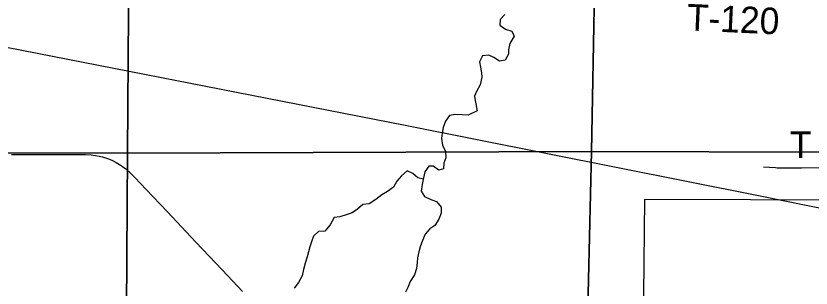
# Model space of a CAD drawing. Extents: x 0 to 34, y 0 to 22.
# Drawn here: x 4.352 to 5.204, y 18.771 to 19.063 of the extents above; entities that cross this region are included whole.
import ezdxf

# ---------------------------------------------------------------- set-up
doc = ezdxf.new("R2010")
doc.units = 0
for name, color, linetype in [('GM_X_County_Road', 7, 'Continuous'), ('GM_X_Minor_River', 7, 'Continuous'), ('GM_X_Rail_Line', 7, 'Continuous'), ('GM_X_Section', 7, 'Continuous'), ('GM_X_Township_Road', 7, 'Continuous'), ('GM_X_Township_Road_Text', 7, 'Continuous')]:
    doc.layers.add(name, color=color, linetype=linetype)

msp = doc.modelspace()

# ---------------------------------------------------------------- linework, layer by layer
at = {"layer": 'GM_X_County_Road'}
msp.add_lwpolyline([(4.3471, 18.91407), (4.37396, 18.91403), (4.40566, 18.91404), (4.42322, 18.91401), (4.42638, 18.91401), (4.43259, 18.91364), (4.43732, 18.91302), (4.44114, 18.91241), (4.44452, 18.91163), (4.44678, 18.91101), (4.44908, 18.91027), (4.452, 18.90912), (4.45599, 18.9074), (4.45932, 18.90563), (4.46286, 18.90357), (4.46619, 18.90131), (4.46973, 18.89864), (4.47429, 18.89461), (4.47939, 18.8896), (4.49153, 18.87673), (4.51382, 18.85305), (4.5292, 18.83679), (4.54475, 18.82025), (4.56605, 18.79764), (4.57889, 18.78411), (4.59481, 18.7673)], dxfattribs=at)
at = {"layer": 'GM_X_Minor_River'}
for points in [[(4.87582, 19.0644), (4.87086, 19.05892), (4.87063, 19.05285), (4.87648, 19.04864), (4.88347, 19.04632), (4.88571, 19.04118), (4.88131, 19.03323), (4.87975, 19.02641), (4.87972, 19.02166), (4.87627, 19.01542), (4.8702, 19.01431), (4.86398, 19.01834), (4.85888, 19.02084), (4.85187, 19.01993), (4.84861, 19.01368), (4.8499, 19.00798), (4.851, 19.00171), (4.85116, 18.99696), (4.8494, 18.989), (4.84557, 18.98181), (4.84327, 18.97688), (4.84399, 18.97194), (4.84635, 18.9611)], [(4.84635, 18.9611), (4.8364, 18.95642), (4.82995, 18.95666), (4.82293, 18.9571), (4.81647, 18.956), (4.81225, 18.94977), (4.80993, 18.94296), (4.80874, 18.93709), (4.80813, 18.9314), (4.80922, 18.92418), (4.81221, 18.91752), (4.81273, 18.91068), (4.81041, 18.90482), (4.81017, 18.89875), (4.80504, 18.89746), (4.79919, 18.90149), (4.79445, 18.90171), (4.79004, 18.89567), (4.78885, 18.88904), (4.7871, 18.88203), (4.7861, 18.87483), (4.78966, 18.8693), (4.79666, 18.86602), (4.80271, 18.8637), (4.8076, 18.85759), (4.80774, 18.85114), (4.80523, 18.84471), (4.80082, 18.8381), (4.79548, 18.83434), (4.79051, 18.82888), (4.78761, 18.82207), (4.78509, 18.81507), (4.78373, 18.80996), (4.78235, 18.80332), (4.78175, 18.79821), (4.78113, 18.79195), (4.779, 18.78532), (4.77439, 18.77796), (4.77188, 18.77153), (4.76938, 18.76661)], [(4.78854, 18.88781), (4.78278, 18.88928), (4.77712, 18.89368), (4.77126, 18.89657), (4.76515, 18.89131), (4.76018, 18.88546), (4.75653, 18.87904), (4.75004, 18.87453), (4.74413, 18.87078), (4.73765, 18.8659), (4.73059, 18.86121), (4.72376, 18.86069), (4.71803, 18.85561), (4.71212, 18.85167), (4.70565, 18.84963), (4.69919, 18.84721), (4.69292, 18.8465), (4.68869, 18.83894), (4.68295, 18.83215), (4.6763, 18.83163), (4.67077, 18.82655), (4.66883, 18.82163), (4.66689, 18.81519), (4.66533, 18.80989), (4.66397, 18.80459), (4.66202, 18.79758), (4.66007, 18.79077), (4.6585, 18.78395), (4.65485, 18.77696), (4.65025, 18.77073)]]:
    msp.add_lwpolyline(points, dxfattribs=at)
at = {"layer": 'GM_X_Rail_Line'}
msp.add_lwpolyline([(2.6, 19.37601), (2.66227, 19.36364), (3.09112, 19.27847), (3.48984, 19.19924), (3.90426, 19.11632), (4.22655, 19.05166), (4.7691, 18.94555), (5.14758, 18.87009), (5.40664, 18.81773), (5.47207, 18.80597), (5.50091, 18.80172), (5.55499, 18.7934), (5.62633, 18.78234), (5.64273, 18.77969)], dxfattribs=at)
at = {"layer": 'GM_X_Section'}
for points in [[(5.48234, 19.42421), (5.47758, 19.24709), (5.28698, 19.24797), (5.28497, 18.95866), (5.22335, 18.96123), (5.22048, 18.91682), (4.96887, 18.91739), (4.9781, 19.41724)], [(4.47488, 19.41917), (4.47149, 18.91545), (3.98059, 18.9165), (3.98263, 19.41835)], [(4.9781, 19.41724), (4.96887, 18.91739), (4.47149, 18.91545), (4.47488, 19.41917)], [(3.98059, 18.9165), (4.47149, 18.91545), (4.46827, 18.41225), (3.9728, 18.4103)], [(4.47149, 18.91545), (4.96887, 18.91739), (4.95692, 18.41406), (4.46827, 18.41225)], [(4.96887, 18.91739), (5.22048, 18.91682), (5.36618, 18.91648), (5.36674, 18.86475), (5.0257, 18.8658), (5.02156, 18.49258), (5.46515, 18.49757), (5.46379, 18.41876), (4.95692, 18.41406)]]:
    msp.add_lwpolyline(points, close=True, dxfattribs=at)
at = {"layer": 'GM_X_Township_Road'}
msp.add_lwpolyline([(5.15321, 18.90083), (5.15967, 18.90043), (5.16584, 18.90008), (5.16781, 18.89997), (5.17525, 18.89998), (5.1939, 18.90003), (5.23644, 18.90008), (5.2734, 18.90029), (5.28093, 18.90025), (5.28366, 18.90024)], dxfattribs=at)

# ---------------------------------------------------------------- texts
at = {"layer": 'GM_X_Township_Road_Text'}
for s, height, rotation, p in [('T-120', 0.028409, 357.39615, (5.07033, 19.04731)), ('T', 0.02841, 0.0932, (5.18137, 18.91058))]:
    msp.add_text(s, height=height, rotation=rotation, dxfattribs=at).set_placement(p)

doc.saveas('drawing.dxf')
